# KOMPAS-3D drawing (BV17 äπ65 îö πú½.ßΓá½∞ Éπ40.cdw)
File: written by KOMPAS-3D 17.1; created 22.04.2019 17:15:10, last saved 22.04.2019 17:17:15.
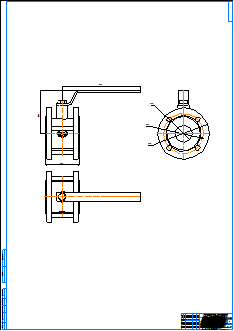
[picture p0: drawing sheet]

Sheet 1: A0, portrait

Title block, sheet 1: name: BV17 Ду65 МФ угл.сталь Ру40; material: Внимание! Данный продукт является объектом авторского права ООО «Торговый Дом АДЛ». / Запрещается изменение, копирование, распространение / (в том числе путем копирования на другие сайты и ресурсы в Интернете) / или любое иное использование информации и объектов без предварительного / согласия правообладателя (ООО «Торговый Дом АДЛ»).; mass: 12,53; sheets: 1; organisation: ООО "Торговый дом АДЛ"; sheet format: A0; stored path: \\adlc.lan\data\АДЛ_ПКД\3D-модели\ADL production\Краны шаровые серии BV\BV17 МФ угл.сталь Ру40\KOMPAS 2D\BV17 Ду65 МФ угл.сталь Ру40.cdw

Views: Вид 1, Проекционный вид 2, Проекционный вид 3
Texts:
  user
Dimensions and other numbers on the sheet: 280; 154; 145; 123; 62; 185; 1:1; 1; 12,53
